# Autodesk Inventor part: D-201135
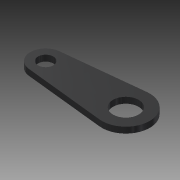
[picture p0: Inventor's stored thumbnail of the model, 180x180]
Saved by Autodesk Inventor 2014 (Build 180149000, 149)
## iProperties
Created: 2007-10
Part Number: D-201135
Document SubType Name: Modeling
Designer: TH
Density: 7.85 g/cm^3
Mass: 34.6613 g
Surface Area: 33.8 cm^2
Volume: 4.41545 cm^3
Material: Steel
Description: PIVOT PLATE
Appearance: Rubber - Black - Version 1.1
Component Category: Lower Component
Author: TH
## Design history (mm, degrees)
sketch "Sketch1"
  geometry: L1 (0, 0)-(-47, 0); L2 (-47.957, 8.949)-(-1.489, 13.921); L3 (-47.957, -8.949)-(-1.489, -13.921); A1 r 14 centre (0, 0) between (-1.489, -13.921) and (-1.489, 13.921); A2 r 9 centre (-47, 0) between (-47.957, 8.949) and (-47.957, -8.949); 1 further point
  constraints: 6 end point, 4 point on circle, 4 tangent, 2 centre point, 2 coincident, 1 horizontal
  dimensions: "d0" = 18 diameter of A2; "d1" = 28 diameter of A1; "d2" = 47 distance of point (0, 0) L1.end
extrude "Extrusion1" new body sketch "Sketch1" stored distance "d3" = 3.5 (= Thickness); taper "d4" = 0 deg
sketch "Sketch2"
  geometry: A1 r 14 centre (0, 0) between (-1.489, -13.921) and (-1.489, 13.921) reference
hole "Hole1" sketch "Sketch2" at (0, 0) diameter "d5" = 15 (= Rod_Major_Diameter); stored, may be unused: countersink angle "d9" = 90 deg, drill point angle "d11" = 118 deg; dims "d6" = 6, "d7" = 4, "d8" = 2, "d10" = 8
sketch "Sketch3"
  geometry: A1 r 9 centre (-47, 0) between (-47.957, 8.949) and (-47.957, -8.949) reference
hole "Hole2" sketch "Sketch3" at (-47, 0) diameter "d12" = 9; stored, may be unused: countersink angle "d16" = 90 deg, drill point angle "d18" = 118 deg; dims "d13" = 6, "d14" = 4, "d15" = 2, "d17" = 8
node "200987" dims "d19" = 10
body "Solid1"
other parameters: "Thickness" = 3.5 [user parameter; used in 1 equation term], "Rod_Major_Diameter" = 15
